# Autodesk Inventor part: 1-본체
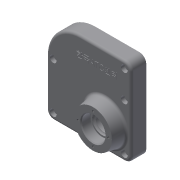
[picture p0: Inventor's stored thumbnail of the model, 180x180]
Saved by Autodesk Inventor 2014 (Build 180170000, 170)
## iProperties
Created: 2015-11
Part Number: 1-본체
Material: 일반
Document SubType Name: Modeling
Designer: SURY
Density: 1 g/cm^3
Appearance: 기본값
Author: SURY
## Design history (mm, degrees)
sketch "스케치1"
  geometry: L1 (-50, 51.5)-(10, 51.5); L2 (50, 11.5)-(50, -51.5); L3 (50, -51.5)-(-50, -51.5); L4 (-50, -51.5)-(-50, 51.5); L5 (10, 47.5)-(-46, 47.5); L6 (-46, 47.5)-(-46, -47.5); L7 (-46, -47.5)-(46, -47.5); L8 (46, -47.5)-(46, 11.5); C1 r 6 at (-42, 43.5); C2 r 6 at (42, 11.5); C3 r 6 at (42, -43.5); C4 r 6 at (-42, -43.5); C5 r 6 at (-42, 11.5); A1 r 40 centre (10, 11.5) between (50, 11.5) and (10, 51.5); A2 r 36 centre (10, 11.5) between (46, 11.5) and (10, 47.5); 2 further points
  constraints: 16 end point, 7 centre point, 4 equal radius, 4 parallel, 4 point on circle, 3 vertical alignment, 2 horizontal alignment, 2 perpendicular, 1 horizontal, 1 midpoint, 1 tangent, 4 other
  dimensions: "d0" = 12 diameter of C1; "d1" = 100 distance between parallel lines of L2 L4; "d2" = 103 distance of L3.end L1.start; "d3" = 63 distance from line of L3 C5.centre; "d4" = 8 distance from line of L3 C3.centre; "d5" = 55 distance of C3.centre C2.centre; "d6" = 32 vertical distance of C1.centre C2.centre; "d7" = 84 horizontal distance of C2.centre C1.centre; "d8" = 42 horizontal distance of C1.centre point (0, 0); "d9" = 50 distance from line of L4 point (0, 0); "d10" = 40 radius of A1; "d12" = 60 distance from line of L4 A1.centre; "d13" = 36 radius of A2; "d14" = 4 distance between parallel lines of L3 L7 (derived)
extrude "돌출1" new body sketch "스케치1" distance "d15" = 18; taper "d16" = 0 deg
extrude "돌출2" cut sketch "스케치1" distance "d17" = 14; taper "d18" = 0 deg
extrude "돌출3" join sketch "스케치1" distance "d19" = 14; taper "d20" = 0 deg
sketch "스케치2"
  geometry: L1 (-50, 51.5)-(50, 51.5) reference; L2 (50, 51.5)-(50, -51.5) reference; C1 r 20 at (20, 21.5); C2 r 20 at (-10, -11.5); 1 further point
  constraints: 2 centre point
  dimensions: "d21" = 40 diameter of C2; "d22" = 40 diameter of C1; "d23" = 63 distance from line of L1 C2.centre; "d24" = 60 distance from line of L2 C2.centre; "d25" = 30 distance from line of L2 C1.centre; "d26" = 30 distance from line of L1 C1.centre
extrude "돌출4" join sketch "스케치2" distance "d27" = 11; taper "d28" = -10 deg
sketch "스케치3"
  geometry: L1 (50, -51.5)-(50, 51.5) reference; L2 (-50, -51.5)-(50, -51.5) reference; C1 r 25 at (20, -21.5); 1 further point
  constraints: 1 centre point
  dimensions: "d29" = 30 distance from line of L1 C1.centre; "d30" = 30 distance from line of C1.centre L2; "d31" = 50 diameter of C1
extrude "돌출5" join sketch "스케치3" distance "d32" = 15; taper "d33" = -10 deg
fillet "모깎기1" dims "d34" = 8, "d35" = 3
sketch "스케치4"
  geometry: C1 r 18.06 at (30, 33) reference; C2 r 18.06 at (0, 0) reference; 3 further points
  constraints: 2 coincident
  node "투영된 루프1"
  node "투영된 루프2"
hole "구멍1" diameter "d38" = 20; stored, may be unused: countersink angle "d42" = 90 deg, drill point angle "d44" = 118 deg; dims "d36" = 10, "d37" = 10, "d39" = 6, "d40" = 32, "d41" = 9, "d43" = 8
hole "구멍2" diameter "d47" = 22; stored, may be unused: countersink angle "d51" = 90 deg, drill point angle "d53" = 0 deg; dims "d45" = 10, "d46" = 10, "d48" = 6, "d49" = 32, "d50" = 9, "d52" = 2
sketch "스케치5"
  geometry: C1 r 10 at (0, 0) reference; C2 r 22.355 at (0, 0) reference; 2 further points
  constraints: 1 coincident
  node "투영된 루프3"
hole "구멍3" diameter "d56" = 24; stored, may be unused: countersink angle "d60" = 90 deg, drill point angle "d62" = 0 deg; dims "d54" = 10, "d55" = 10, "d57" = 6, "d58" = 28, "d59" = 11, "d61" = 2
fillet "모깎기2" dims "d63" = 0.3, "d64" = 3
chamfer "모따기1" distance "d65" = 1; stored, may be unused: second distance "d66" = 2, angle "d67" = 45 deg
sketch "스케치6"
  geometry: L1 (50, -43.5)-(50, 43.5) reference; L2 (-42, -51.5)-(42, -51.5) reference; 6 further points
  constraints: 3 vertical alignment, 2 horizontal alignment
  dimensions: "d72" = 8 distance from line of point (-42, -43.5) L2; "d73" = 55 distance of point (-42, -43.5) point (-42, 11.5); "d74" = 32 vertical distance of point (-42, 11.5) point (42, 43.5); "d75" = 84 horizontal distance of point (-42, 11.5) point (42, 43.5); "d76" = 42 horizontal distance of point (-42, 11.5) point (0, 0)
hole "구멍4" sketch "스케치6" at (-42, -43.5), (-42, 11.5), (42, -43.5), (42, 43.5), (42, 11.5) diameter "d77" = 4.5; stored, may be unused: countersink angle "d81" = 90 deg, drill point angle "d83" = 0 deg; dims "d78" = 6, "d79" = 8, "d80" = 4.4, "d82" = 2
sketch "스케치7" dims "d84" = 36
  geometry: L1 (30, -22)-(30, 65) reference; L2 (-62, -30)-(22, -30) reference; 3 further points
  constraints: 2 vertical alignment, 2 other
  dimensions: "d85" = 30 distance from line of L1 point (0, 0); "d86" = 30 distance from line of L2 point (0, 0)
hole "구멍5" sketch "스케치7" at (0, 18) diameter "d87" = 2.459; stored, may be unused: countersink angle "d91" = 90 deg, drill point angle "d93" = 118 deg; dims "d88" = 8, "d89" = 32, "d90" = 9, "d92" = 10
sketch "스케치8"
  geometry: L1 (-14.887, 35.102)-(34.887, 35.102); L2 (34.887, 35.102)-(34.887, 27.898); L3 (34.887, 27.898)-(-14.887, 27.898); L4 (-14.887, 27.898)-(-14.887, 35.102); L5 (-14.887, 31.5)-(34.887, 31.5); L6 (10, 35.102)-(10, 27.898); L7 (42, 51.5)-(-10, 51.5) reference; L8 (50, -43.5)-(50, 43.5) reference; 2 further points
  constraints: 5 midpoint, 4 end point, 2 other
  dimensions: "d97" = 20 distance from line of point (10, 31.5) L7; "d98" = 40 distance from line of point (10, 31.5) L8
feature "엠보싱1" sketch "스케치8" dims "d0" = 12, "d1" = 100, "d2" = 103, "d3" = 63, "d4" = 8, "d5" = 55, "d6" = 32, "d7" = 84, "d8" = 42, "d9" = 50, "d10" = 40, "d12" = 60, "d13" = 36, "d14" = 4 (derived), "d99" = 0.5, "d100" = 0
node "솔리드1"
pattern_circular "원형 패턴1" dims angle "d95" = 360 deg
